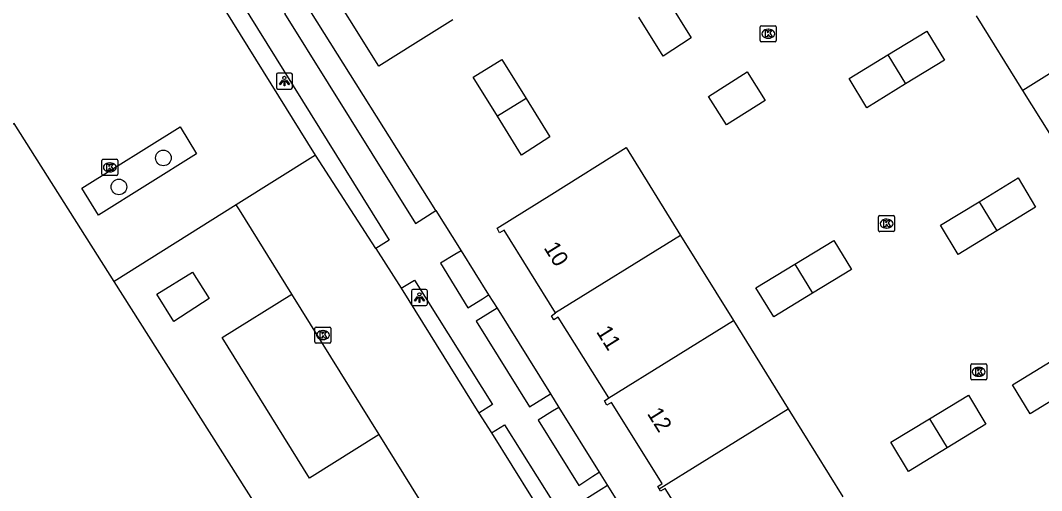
# Model space of a CAD drawing. Extents: x 159280 to 160375, y 384531 to 385872.
# Drawn here: x 159467.8 to 159531.5, y 385362.2 to 385391.6 of the extents above; entities that cross this region are included whole.
import ezdxf

# ---------------------------------------------------------------- set-up
doc = ezdxf.new("R2010")
doc.units = 0
for name, color, linetype in [('IMGEO_Boom', 7, 'Continuous'), ('IMGEO_Groenvoorziening', 7, 'Continuous'), ('IMGEO_Kolk', 7, 'Continuous'), ('IMGEO_Lage_trafo', 7, 'Continuous'), ('IMGEO_Lichtpunt', 7, 'Continuous'), ('IMGEO_Pand', 7, 'Continuous'), ('IMGEO_Pand_nummerreeks', 7, 'Continuous'), ('IMGEO_Parkeervlak_open', 7, 'Continuous'), ('IMGEO_Rijbaan_lokaal_open', 7, 'Continuous'), ('IMGEO_Voetgangersgebied_open', 7, 'Continuous'), ('IMGEO_Voetpad_open', 7, 'Continuous')]:
    doc.layers.add(name, color=color, linetype=linetype)

msp = doc.modelspace()

# ---------------------------------------------------------------- linework, layer by layer
at = {"layer": 'IMGEO_Boom'}
for centre in [(159476.677, 385383.014), (159473.904, 385381.203)]:
    msp.add_circle(centre, 0.489, dxfattribs=at)
at = {"layer": 'IMGEO_Groenvoorziening'}
for points in [[(159493.699, 385379.74), (159485.468, 385392.81)], [(159495.271, 385377.219), (159496.989, 385374.464)], [(159497.511, 385373.627), (159500.843, 385368.283)], [(159501.367, 385367.441), (159503.891, 385363.393)], [(159504.415, 385362.553), (159507.722, 385357.249)]]:
    msp.add_lwpolyline(points, dxfattribs=at)
at = {"layer": 'IMGEO_Kolk'}
for p, q in [((159513.946, 385390.34), (159513.946, 385391.192)), ((159514.021, 385391.266), (159514.873, 385391.266)), ((159514.434, 385391.046), (159514.459, 385391.046)), ((159514.947, 385391.192), (159514.947, 385390.34)), ((159514.457, 385390.486), (159514.432, 385390.486)), ((159514.873, 385390.266), (159514.021, 385390.266)), ((159472.834, 385382.001), (159472.834, 385382.853)), ((159472.909, 385382.927), (159473.761, 385382.927)), ((159473.835, 385382.853), (159473.835, 385382.001)), ((159473.345, 385382.147), (159473.32, 385382.147)), ((159473.322, 385382.707), (159473.347, 385382.707)), ((159473.761, 385381.927), (159472.909, 385381.927)), ((159521.334, 385378.485), (159521.334, 385379.337)), ((159521.409, 385379.411), (159522.261, 385379.411)), ((159521.822, 385379.191), (159521.847, 385379.191)), ((159522.335, 385379.337), (159522.335, 385378.485)), ((159522.261, 385378.411), (159521.409, 385378.411)), ((159521.845, 385378.631), (159521.82, 385378.631)), ((159486.141, 385371.529), (159486.141, 385372.381)), ((159486.216, 385372.455), (159487.068, 385372.455)), ((159486.629, 385372.235), (159486.654, 385372.235)), ((159487.142, 385372.381), (159487.142, 385371.529)), ((159487.068, 385371.455), (159486.216, 385371.455)), ((159486.652, 385371.675), (159486.627, 385371.675)), ((159527.086, 385369.234), (159527.086, 385370.086)), ((159527.161, 385370.16), (159528.013, 385370.16)), ((159528.087, 385370.086), (159528.087, 385369.234)), ((159527.597, 385369.38), (159527.572, 385369.38)), ((159527.574, 385369.94), (159527.599, 385369.94)), ((159528.013, 385369.16), (159527.161, 385369.16))]:
    msp.add_line(p, q, dxfattribs=at)
for points in [[(159513.946, 385390.34), (159513.946, 385391.192)], [(159514.021, 385391.266), (159514.873, 385391.266)], [(159514.947, 385391.192), (159514.947, 385390.34)], [(159514.267, 385390.966), (159514.39, 385390.966), (159514.39, 385390.815), (159514.52, 385390.966), (159514.684, 385390.966), (159514.538, 385390.815), (159514.691, 385390.566), (159514.539, 385390.566), (159514.454, 385390.73), (159514.39, 385390.663), (159514.39, 385390.566), (159514.267, 385390.566), (159514.267, 385390.966)], [(159514.873, 385390.266), (159514.021, 385390.266)], [(159472.834, 385382.001), (159472.834, 385382.853)], [(159472.909, 385382.927), (159473.761, 385382.927)], [(159473.835, 385382.853), (159473.835, 385382.001)], [(159473.155, 385382.627), (159473.278, 385382.627), (159473.278, 385382.476), (159473.408, 385382.627), (159473.572, 385382.627), (159473.426, 385382.476), (159473.579, 385382.227), (159473.427, 385382.227), (159473.342, 385382.391), (159473.278, 385382.324), (159473.278, 385382.227), (159473.155, 385382.227), (159473.155, 385382.627)], [(159473.761, 385381.927), (159472.909, 385381.927)], [(159521.334, 385378.485), (159521.334, 385379.337)], [(159521.409, 385379.411), (159522.261, 385379.411)], [(159521.655, 385379.111), (159521.778, 385379.111), (159521.778, 385378.96), (159521.908, 385379.111), (159522.072, 385379.111), (159521.926, 385378.96), (159522.079, 385378.711), (159521.927, 385378.711), (159521.842, 385378.875), (159521.778, 385378.808), (159521.778, 385378.711), (159521.655, 385378.711), (159521.655, 385379.111)], [(159522.335, 385379.337), (159522.335, 385378.485)], [(159522.261, 385378.411), (159521.409, 385378.411)], [(159486.141, 385371.529), (159486.141, 385372.381)], [(159486.216, 385372.455), (159487.068, 385372.455)], [(159486.462, 385372.155), (159486.585, 385372.155), (159486.585, 385372.004), (159486.715, 385372.155), (159486.879, 385372.155), (159486.733, 385372.004), (159486.886, 385371.755), (159486.734, 385371.755), (159486.649, 385371.919), (159486.585, 385371.852), (159486.585, 385371.755), (159486.462, 385371.755), (159486.462, 385372.155)], [(159487.142, 385372.381), (159487.142, 385371.529)], [(159487.068, 385371.455), (159486.216, 385371.455)], [(159527.086, 385369.234), (159527.086, 385370.086)], [(159527.161, 385370.16), (159528.013, 385370.16)], [(159528.087, 385370.086), (159528.087, 385369.234)], [(159527.407, 385369.86), (159527.53, 385369.86), (159527.53, 385369.709), (159527.66, 385369.86), (159527.824, 385369.86), (159527.678, 385369.709), (159527.831, 385369.46), (159527.679, 385369.46), (159527.594, 385369.624), (159527.53, 385369.557), (159527.53, 385369.46), (159527.407, 385369.46), (159527.407, 385369.86)], [(159528.013, 385369.16), (159527.161, 385369.16)]]:
    msp.add_lwpolyline(points, dxfattribs=at)
for centre, start, end in [((159514.023, 385391.19), 91.55205, 178.44795), ((159514.023, 385391.19), 91.55205, 178.44795), ((159514.871, 385391.19), 1.55205, 88.44795), ((159514.871, 385391.19), 1.55205, 88.44795), ((159514.023, 385390.342), 181.55205, 268.44795), ((159514.023, 385390.342), 181.55205, 268.44795), ((159514.871, 385390.342), 271.55205, 358.44795), ((159514.871, 385390.342), 271.55205, 358.44795), ((159472.911, 385382.851), 91.55205, 178.44795), ((159472.911, 385382.851), 91.55205, 178.44795), ((159473.759, 385382.851), 1.55205, 88.44795), ((159473.759, 385382.851), 1.55205, 88.44795), ((159472.911, 385382.003), 181.55205, 268.44795), ((159472.911, 385382.003), 181.55205, 268.44795), ((159473.759, 385382.003), 271.55205, 358.44795), ((159473.759, 385382.003), 271.55205, 358.44795), ((159521.411, 385379.335), 91.55205, 178.44795), ((159521.411, 385379.335), 91.55205, 178.44795), ((159522.259, 385379.335), 1.55205, 88.44795), ((159522.259, 385379.335), 1.55205, 88.44795), ((159521.411, 385378.487), 181.55205, 268.44795), ((159521.411, 385378.487), 181.55205, 268.44795), ((159522.259, 385378.487), 271.55205, 358.44795), ((159522.259, 385378.487), 271.55205, 358.44795), ((159486.218, 385372.379), 91.55205, 178.44795), ((159486.218, 385372.379), 91.55205, 178.44795), ((159487.066, 385372.379), 1.55205, 88.44795), ((159487.066, 385372.379), 1.55205, 88.44795), ((159486.218, 385371.531), 181.55205, 268.44795), ((159486.218, 385371.531), 181.55205, 268.44795), ((159487.066, 385371.531), 271.55205, 358.44795), ((159487.066, 385371.531), 271.55205, 358.44795), ((159527.163, 385370.084), 91.55205, 178.44795), ((159527.163, 385370.084), 91.55205, 178.44795), ((159528.011, 385370.084), 1.55205, 88.44795), ((159528.011, 385370.084), 1.55205, 88.44795), ((159527.163, 385369.236), 181.55205, 268.44795), ((159527.163, 385369.236), 181.55205, 268.44795), ((159528.011, 385369.236), 271.55205, 358.44795), ((159528.011, 385369.236), 271.55205, 358.44795)]:
    msp.add_arc(centre, 0.0765, start, end, dxfattribs=at)
for centre, major_axis, ratio, start_param, end_param in [((159514.433, 385390.766), (-0.387, 0.002), 0.722429, 4.712389, 7.853982), ((159514.458, 385390.766), (-0.39, 0.002), 0.717154, 1.570796, 4.712389), ((159473.321, 385382.427), (-0.387, 0.002), 0.722429, 4.712389, 7.853982), ((159473.346, 385382.427), (-0.39, 0.002), 0.717154, 1.570796, 4.712389), ((159521.821, 385378.911), (-0.387, 0.002), 0.722429, 4.712389, 7.853982), ((159521.846, 385378.911), (-0.39, 0.002), 0.717154, 1.570796, 4.712389), ((159486.628, 385371.955), (-0.387, 0.002), 0.722429, 4.712389, 7.853982), ((159486.653, 385371.955), (-0.39, 0.002), 0.717154, 1.570796, 4.712389), ((159527.573, 385369.66), (-0.387, 0.002), 0.722429, 4.712389, 7.853982), ((159527.598, 385369.66), (-0.39, 0.002), 0.717154, 1.570796, 4.712389)]:
    msp.add_ellipse(centre, major_axis=major_axis, ratio=ratio, start_param=start_param, end_param=end_param, dxfattribs=at)
at = {"layer": 'IMGEO_Lage_trafo'}
msp.add_lwpolyline([(159477.335, 385372.811), (159476.278, 385374.505), (159478.489, 385375.888), (159479.536, 385374.233), (159477.335, 385372.811)], dxfattribs=at)
at = {"layer": 'IMGEO_Lichtpunt'}
for p, q in [((159483.736, 385388.213), (159483.736, 385387.406)), ((159483.736, 385388.213), (159483.736, 385387.406)), ((159484.638, 385388.308), (159483.83, 385388.308)), ((159484.638, 385388.308), (159483.83, 385388.308)), ((159484.732, 385387.406), (159484.732, 385388.213)), ((159484.732, 385387.406), (159484.732, 385388.213)), ((159483.83, 385387.312), (159484.638, 385387.312)), ((159483.83, 385387.312), (159484.638, 385387.312)), ((159492.167, 385374.702), (159492.167, 385373.895)), ((159492.167, 385374.702), (159492.167, 385373.895)), ((159493.069, 385374.797), (159492.261, 385374.797)), ((159493.069, 385374.797), (159492.261, 385374.797)), ((159493.163, 385373.895), (159493.163, 385374.702)), ((159493.163, 385373.895), (159493.163, 385374.702)), ((159492.261, 385373.801), (159493.069, 385373.801)), ((159492.261, 385373.801), (159493.069, 385373.801))]:
    msp.add_line(p, q, dxfattribs=at)
for points in [[(159484.11, 385387.877), (159484.149, 385387.849), (159483.961, 385387.587), (159483.923, 385387.614), (159484.11, 385387.877)], [(159484.322, 385387.849), (159484.36, 385387.876), (159484.547, 385387.614), (159484.508, 385387.586), (159484.322, 385387.849)], [(159484.212, 385387.829), (159484.259, 385387.829), (159484.259, 385387.507), (159484.212, 385387.507), (159484.212, 385387.829)], [(159492.541, 385374.366), (159492.58, 385374.338), (159492.392, 385374.076), (159492.354, 385374.103), (159492.541, 385374.366)], [(159492.643, 385374.318), (159492.69, 385374.318), (159492.69, 385373.996), (159492.643, 385373.996), (159492.643, 385374.318)], [(159492.753, 385374.338), (159492.791, 385374.365), (159492.978, 385374.103), (159492.939, 385374.075), (159492.753, 385374.338)]]:
    msp.add_lwpolyline(points, dxfattribs=at)
for centre in [(159484.235, 385388.011), (159492.666, 385374.5)]:
    msp.add_circle(centre, 0.0994, dxfattribs=at)
for centre, start, end in [((159483.83, 385388.213), 90, 180), ((159483.83, 385388.213), 90, 180), ((159484.638, 385388.213), 0, 90), ((159484.638, 385388.213), 0, 90), ((159483.83, 385387.406), 180, 270), ((159483.83, 385387.406), 180, 270), ((159484.638, 385387.406), 270, 0), ((159484.638, 385387.406), 270, 360), ((159492.261, 385374.702), 90, 180), ((159492.261, 385374.702), 90, 180), ((159493.069, 385374.702), 0, 90), ((159493.069, 385374.702), 0, 90), ((159492.261, 385373.895), 180, 270), ((159492.261, 385373.895), 180, 270), ((159493.069, 385373.895), 270, 0), ((159493.069, 385373.895), 270, 360)]:
    msp.add_arc(centre, 0.0946, start, end, dxfattribs=at)
at = {"layer": 'IMGEO_Pand'}
for points in [[(159494.759, 385391.636), (159492.429, 385390.182), (159490.122, 385388.741), (159486.404, 385394.708), (159485.282, 385396.556), (159485.343, 385396.594), (159487.481, 385397.927), (159487.305, 385398.209), (159487.564, 385398.377), (159487.748, 385398.094), (159489.893, 385399.431)], [(159508.154, 385392.903), (159509.637, 385390.515), (159507.879, 385389.363), (159506.37, 385391.795)], [(159539.163, 385392.732), (159530.347, 385387.229)], [(159530.347, 385387.229), (159527.442, 385391.884)], [(159521.916, 385389.441), (159524.354, 385390.925), (159525.441, 385389.11), (159523.026, 385387.631)], [(159497.538, 385385.616), (159496.028, 385388.048), (159497.812, 385389.156), (159499.322, 385386.724)], [(159523.026, 385387.631), (159520.61, 385386.151), (159519.504, 385387.973), (159521.916, 385389.441)], [(159521.916, 385389.441), (159523.026, 385387.631)], [(159510.72, 385386.857), (159513.131, 385388.382), (159514.26, 385386.598), (159511.848, 385385.074), (159510.72, 385386.857)], [(159533.253, 385382.575), (159530.347, 385387.229)], [(159499.322, 385386.724), (159500.805, 385384.336), (159499.047, 385383.184), (159497.538, 385385.616)], [(159499.322, 385386.724), (159497.538, 385385.616)], [(159501.165, 385373.333), (159497.949, 385378.514), (159497.667, 385378.337), (159497.51, 385378.625), (159500.933, 385380.761), (159505.571, 385383.655), (159508.971, 385378.179)], [(159527.605, 385380.28), (159530.043, 385381.764), (159531.13, 385379.949), (159528.715, 385378.47)], [(159528.715, 385378.47), (159526.299, 385376.99), (159525.193, 385378.812), (159527.605, 385380.28)], [(159527.605, 385380.28), (159528.715, 385378.47)], [(159508.971, 385378.179), (159501.165, 385373.333)], [(159508.971, 385378.179), (159512.272, 385372.863)], [(159516.105, 385376.387), (159518.531, 385377.864), (159519.64, 385376.059), (159517.214, 385374.575)], [(159517.214, 385374.575), (159514.787, 385373.09), (159513.681, 385374.912), (159516.105, 385376.387)], [(159516.105, 385376.387), (159517.214, 385374.575)], [(159504.502, 385368.039), (159501.33, 385373.071), (159501.059, 385372.896), (159500.904, 385373.164), (159501.165, 385373.333)], [(159504.502, 385368.039), (159512.272, 385372.863)], [(159512.272, 385372.863), (159515.691, 385367.355)], [(159533.211, 385368.516), (159530.795, 385367.036), (159529.689, 385368.858), (159532.101, 385370.326)], [(159524.515, 385366.729), (159526.953, 385368.213), (159528.04, 385366.398), (159525.625, 385364.919)], [(159507.634, 385362.352), (159507.547, 385362.501), (159507.83, 385362.678), (159504.651, 385367.741), (159504.374, 385367.579), (159504.212, 385367.85), (159504.502, 385368.039)], [(159507.634, 385362.352), (159515.691, 385367.355)], [(159515.691, 385367.355), (159519.102, 385361.861)], [(159525.625, 385364.919), (159523.209, 385363.439), (159522.103, 385365.261), (159524.515, 385366.729)], [(159524.515, 385366.729), (159525.625, 385364.919)], [(159511.339, 385357.041), (159511.055, 385356.868), (159510.882, 385357.158), (159511.164, 385357.337), (159508.002, 385362.379), (159507.714, 385362.215), (159507.634, 385362.352)]]:
    msp.add_lwpolyline(points, dxfattribs=at)
at = {"layer": 'IMGEO_Parkeervlak_open'}
msp.add_lwpolyline([(159490.152, 385365.746), (159485.794, 385363.031), (159480.341, 385371.812), (159484.701, 385374.506)], dxfattribs=at)
at = {"layer": 'IMGEO_Rijbaan_lokaal_open'}
for points in [[(159486.183, 385383.185), (159481.223, 385380.079)], [(159489.952, 385377.357), (159486.183, 385383.185)], [(159484.701, 385374.506), (159481.423, 385379.772), (159481.223, 385380.079)], [(159489.952, 385377.357), (159491.531, 385374.888)], [(159490.152, 385365.746), (159484.701, 385374.506)], [(159491.531, 385374.888), (159496.383, 385367.078)], [(159496.383, 385367.078), (159497.164, 385365.855)], [(159492.658, 385361.728), (159490.152, 385365.746)], [(159497.164, 385365.855), (159502.251, 385357.686)]]:
    msp.add_lwpolyline(points, dxfattribs=at)
at = {"layer": 'IMGEO_Voetgangersgebied_open'}
for points in [[(159486.183, 385383.185), (159479.206, 385394.415), (159480.107, 385394.975)], [(159473.614, 385375.297), (159467.362, 385385.157), (159464.704, 385383.64), (159463.396, 385385.729)], [(159478.755, 385383.278), (159472.627, 385379.444), (159471.579, 385381.123), (159477.724, 385384.954), (159478.755, 385383.278)], [(159481.223, 385380.079), (159473.614, 385375.297)], [(159509.752, 385318.295), (159473.614, 385375.297)]]:
    msp.add_lwpolyline(points, dxfattribs=at)
at = {"layer": 'IMGEO_Voetpad_open'}
for points in [[(159480.107, 385394.975), (159481.493, 385392.803), (159490.781, 385377.889), (159489.952, 385377.357)], [(159485.468, 385392.81), (159484.246, 385392.037), (159492.414, 385378.923), (159493.699, 385379.74)], [(159493.699, 385379.74), (159495.271, 385377.219)], [(159495.271, 385377.219), (159494.88, 385376.983), (159493.977, 385376.438), (159495.696, 385373.662), (159496.599, 385374.222), (159496.989, 385374.464)], [(159491.531, 385374.888), (159492.357, 385375.377), (159497.228, 385367.623), (159496.383, 385367.078)], [(159496.989, 385374.464), (159497.511, 385373.627)], [(159497.511, 385373.627), (159496.213, 385372.829), (159499.549, 385367.472), (159500.843, 385368.283)], [(159500.843, 385368.283), (159501.367, 385367.441)], [(159501.367, 385367.441), (159500.972, 385367.196), (159500.077, 385366.642), (159502.61, 385362.56), (159503.498, 385363.137), (159503.891, 385363.393)], [(159497.164, 385365.855), (159497.974, 385366.357), (159503.068, 385358.235), (159502.251, 385357.686)], [(159503.891, 385363.393), (159504.415, 385362.553)], [(159504.415, 385362.553), (159504.016, 385362.305), (159503.127, 385361.752), (159506.402, 385356.472), (159507.313, 385357.008), (159507.722, 385357.249)]]:
    msp.add_lwpolyline(points, dxfattribs=at)

# ---------------------------------------------------------------- texts
at = {"layer": 'IMGEO_Pand_nummerreeks'}
for s, rotation, p in [('10', 301.8276, (159500.405, 385377.402)), ('11', 302.22867, (159503.676, 385372.163)), ('12', 302.12553, (159506.852, 385367.055))]:
    msp.add_text(s, height=1, rotation=rotation, dxfattribs=at).set_placement(p)

doc.saveas('drawing.dxf')
